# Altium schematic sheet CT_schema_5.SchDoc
size 454 x 443 mm
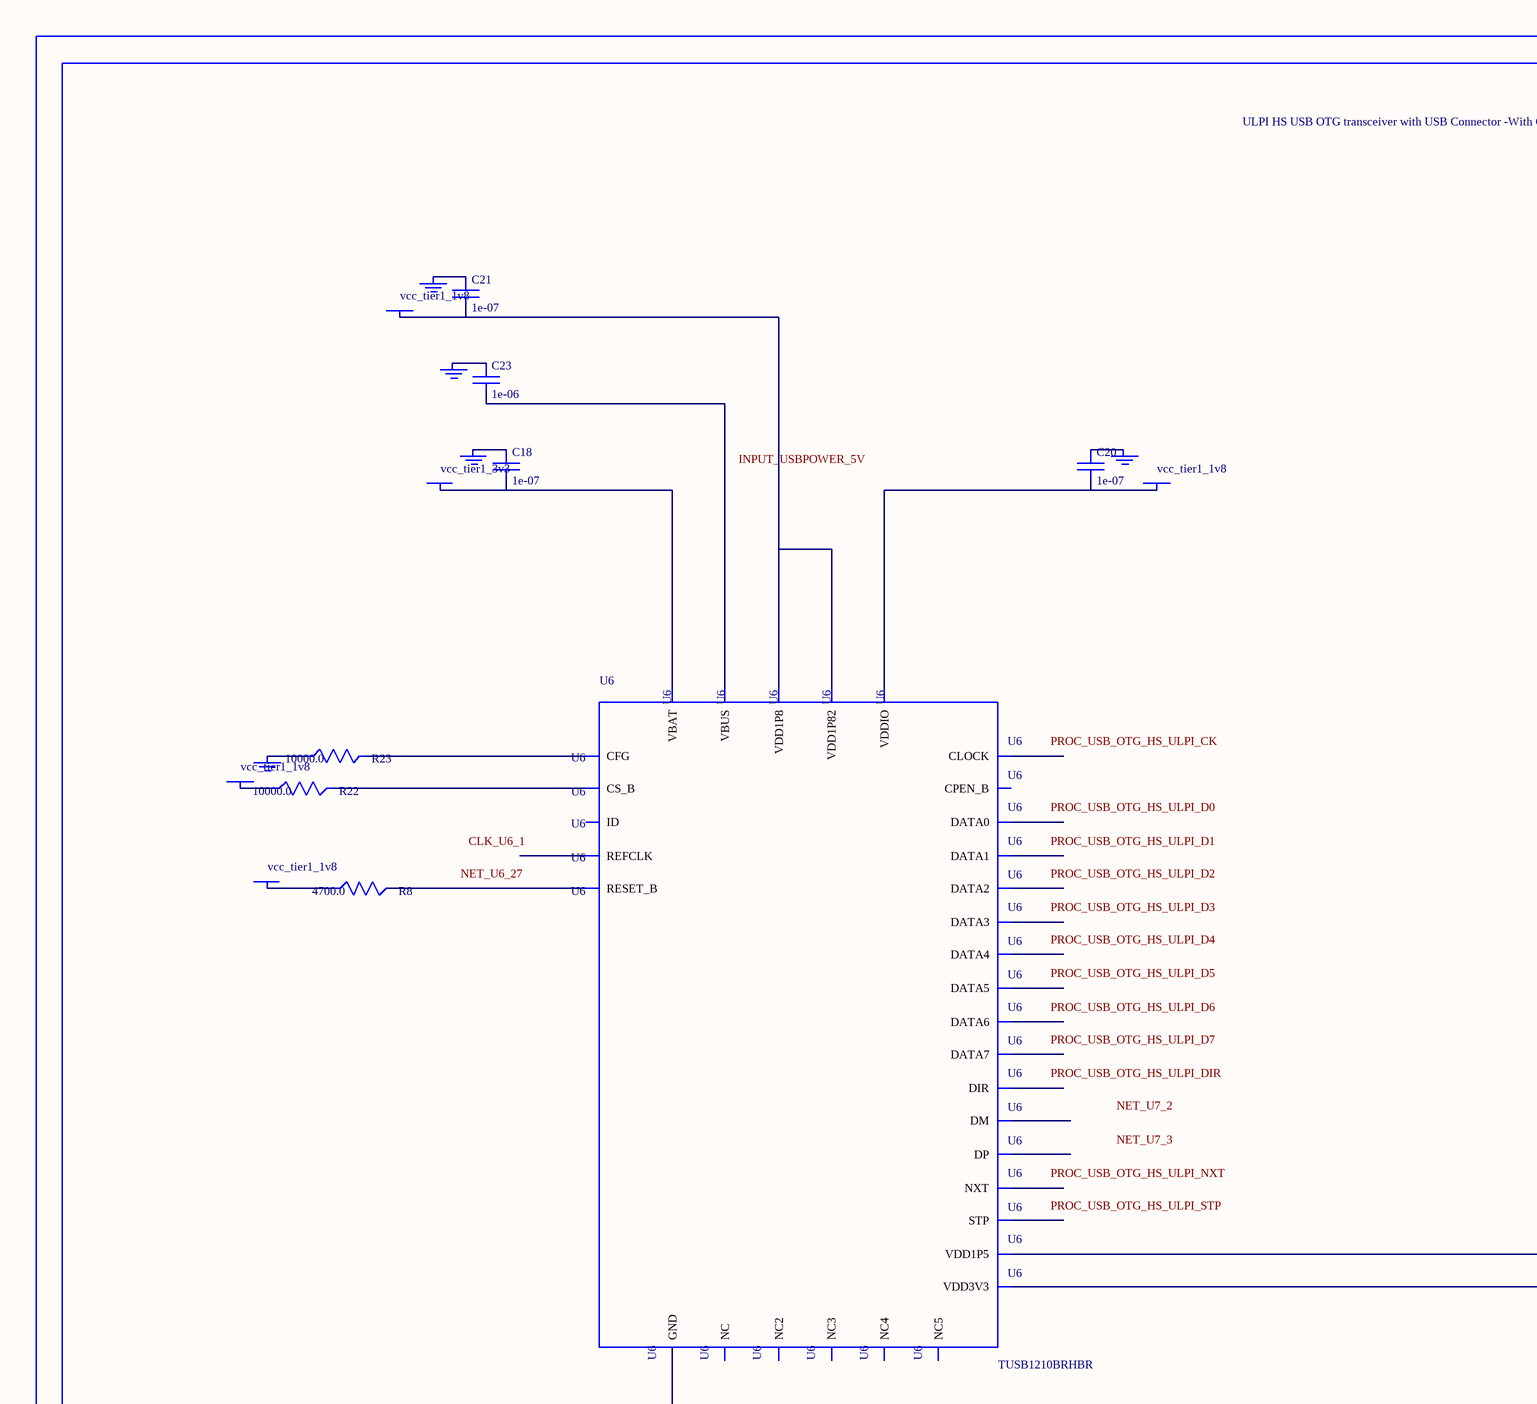
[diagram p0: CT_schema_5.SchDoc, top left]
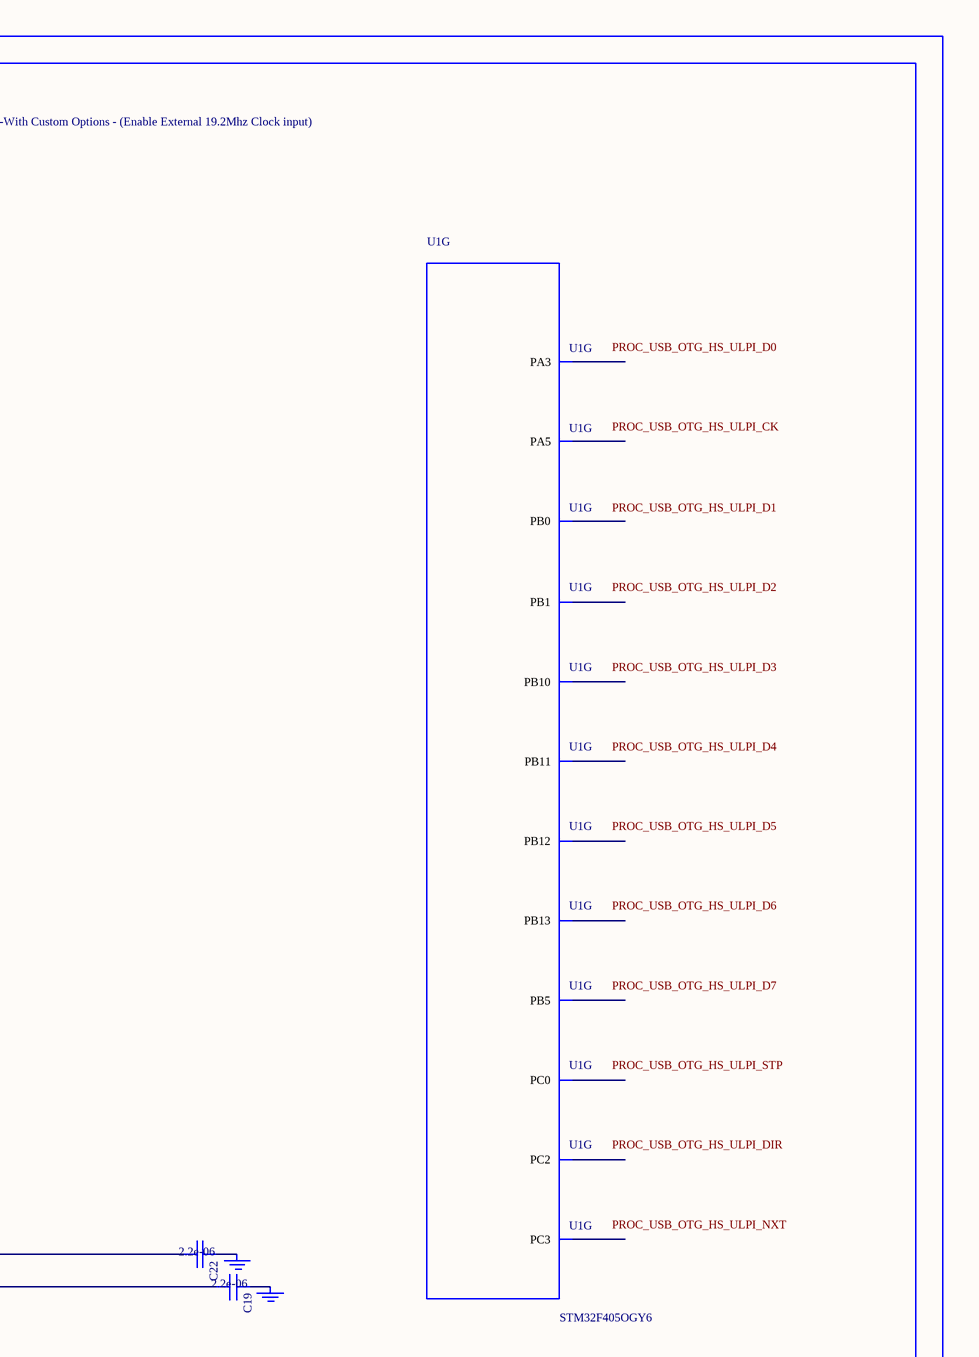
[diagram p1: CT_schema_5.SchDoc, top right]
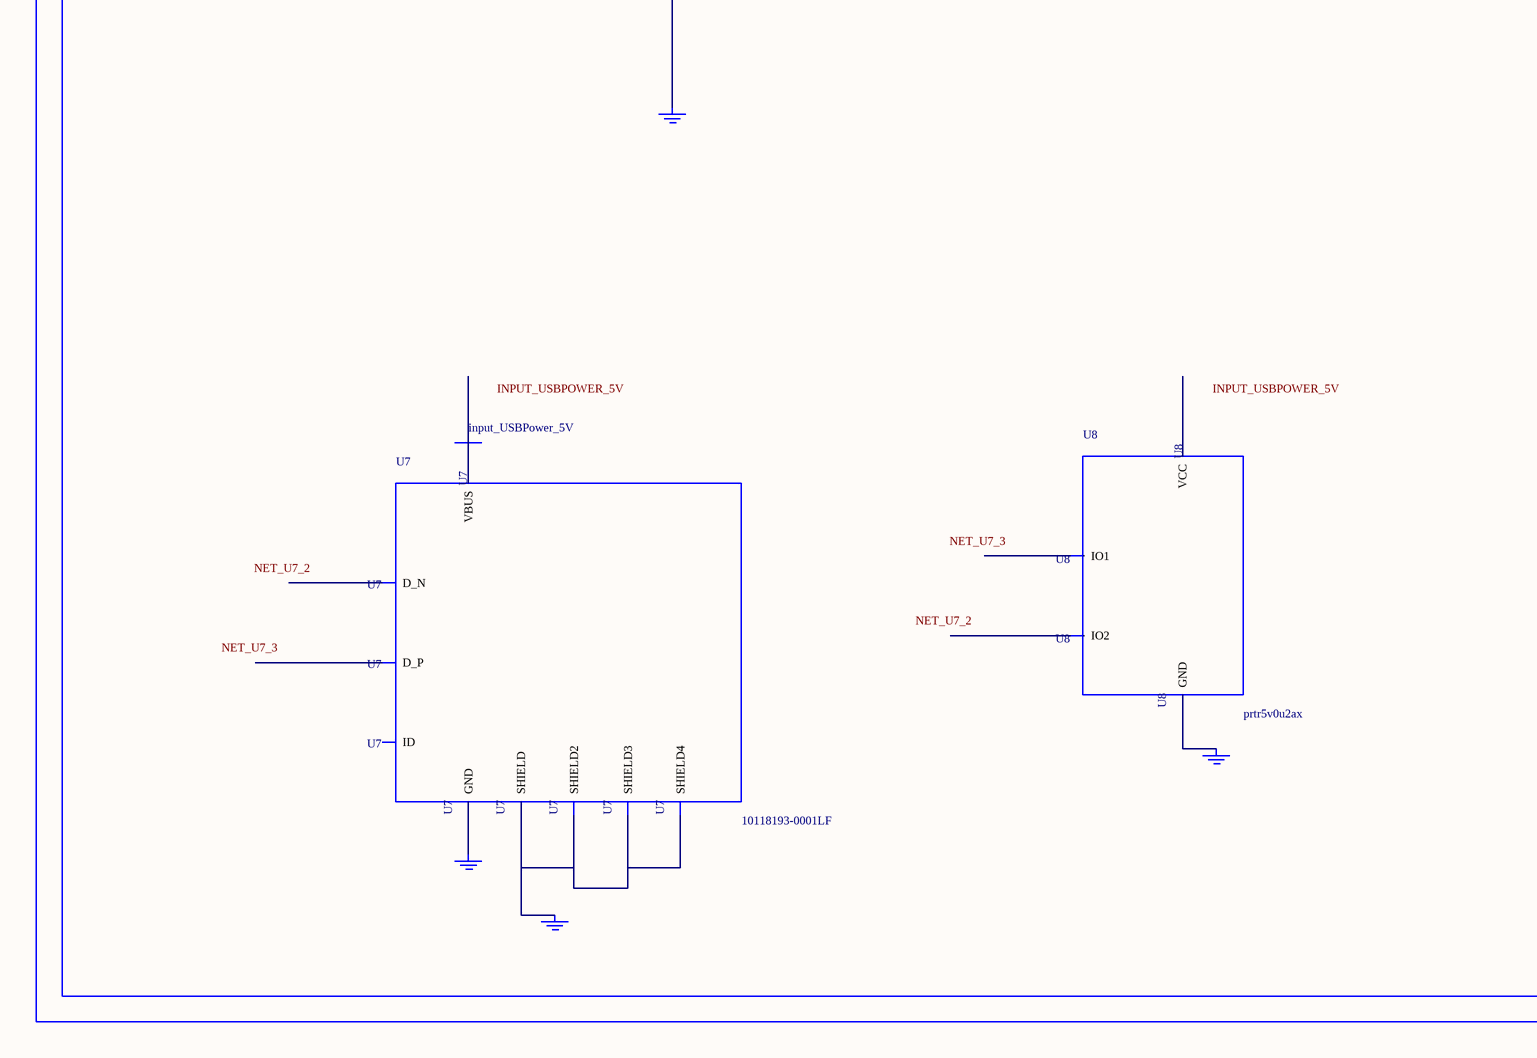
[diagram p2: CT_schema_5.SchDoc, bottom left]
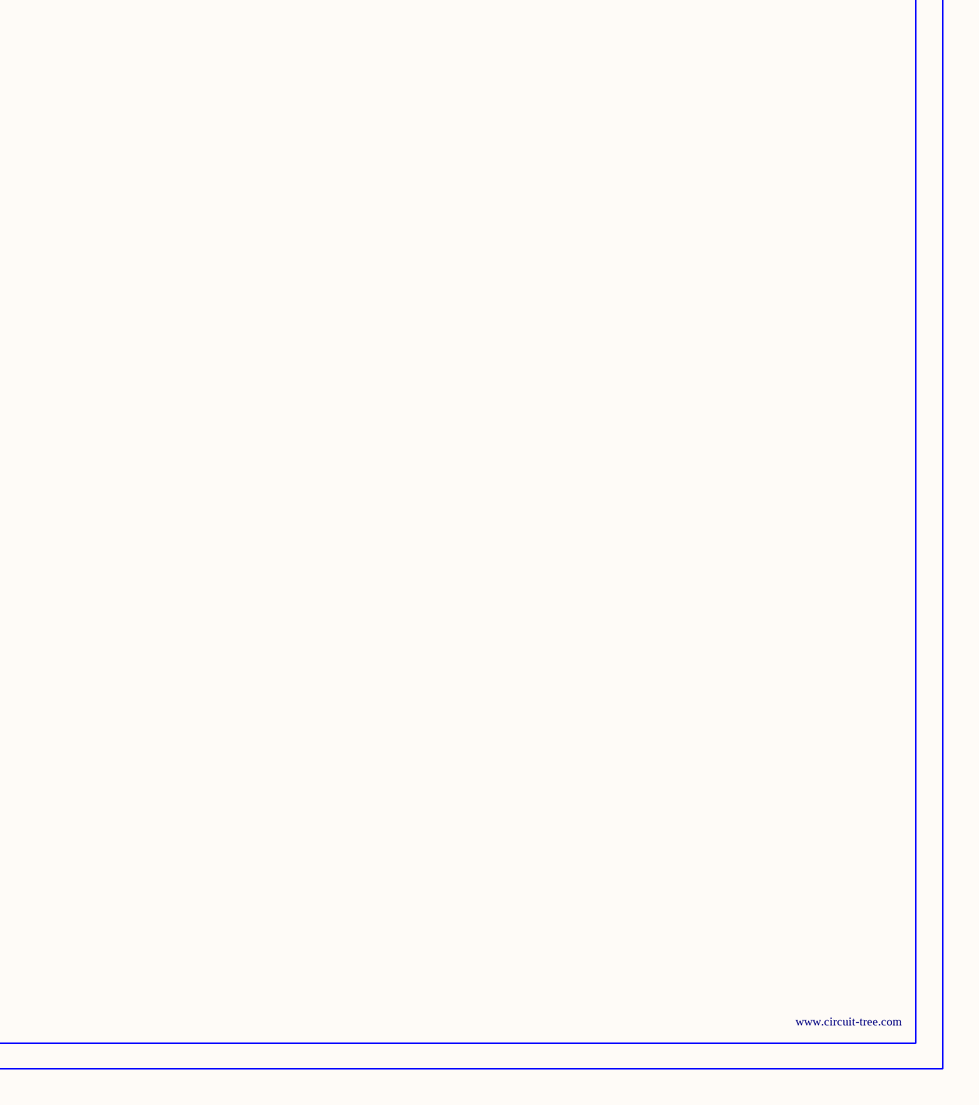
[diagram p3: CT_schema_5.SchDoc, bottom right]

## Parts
BORDER4  (no value)
C18  1e-07  [C0402]
C19  2.2e-06  [C0603]
C20  1e-07  [C0402]
C21  1e-07  [C0402]
C22  2.2e-06  [C0603]
C23  1e-06  [C0603]
GND_INSTANCE_4_0  (no value)
GND_INSTANCE_4_1  (no value)
GND_INSTANCE_4_2  (no value)
GND_INSTANCE_4_3  (no value)
GND_INSTANCE_4_4  (no value)
GND_INSTANCE_4_5  (no value)
GND_INSTANCE_4_6  (no value)
GND_INSTANCE_4_7  (no value)
GND_INSTANCE_4_8  (no value)
GND_INSTANCE_4_9  (no value)
GND_INSTANCE_4_10  (no value)
POWER_INSTANCE_4_0  vcc_tier1_1v8
POWER_INSTANCE_4_1  vcc_tier1_3v3
POWER_INSTANCE_4_2  vcc_tier1_1v8
POWER_INSTANCE_4_3  vcc_tier1_1v8
POWER_INSTANCE_4_4  vcc_tier1_1v8
POWER_INSTANCE_4_5  input_USBPower_5V
R8  4700.0  [R0603]
R22  10000.0  [R0603]
R23  10000.0  [R0603]
U1  STM32F405OGY6  [WLCSP90]  (part G of 9)
U6  TUSB1210BRHBR  [RHB32_3P45X3P45]
U7  10118193-0001LF  [FCI_10118193-0001LF]
U8  prtr5v0u2ax  [SOT143B]

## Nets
NetC18_1: C18.1 GND_INSTANCE_4_3.0(GND)
NetC18_2: C18.2 POWER_INSTANCE_4_1.0(PWR) U6.21(VBAT)
NetC19_1: C19.1 GND_INSTANCE_4_2.0(GND)
NetC19_2: C19.2 U6.20(VDD3V3)
NetC20_1: C20.1 GND_INSTANCE_4_6.0(GND)
NetC20_2: C20.2 POWER_INSTANCE_4_3.0(PWR) U6.32(VDDIO)
NetC21_1: C21.1 GND_INSTANCE_4_5.0(GND)
NetC21_2: C21.2 POWER_INSTANCE_4_2.0(PWR) U6.28(VDD1P8) U6.30(VDD1P82)
NetC22_1: C22.1 GND_INSTANCE_4_0.0(GND)
NetC22_2: C22.2 U6.12(VDD1P5)
NetC23_1: C23.1 GND_INSTANCE_4_4.0(GND)
NetC23_2: C23.2 U6.22(VBUS)
NetGND_INSTANCE_4_1_0: GND_INSTANCE_4_1.0(GND) R23.1
NetGND_INSTANCE_4_7_0: GND_INSTANCE_4_7.0(GND) U6.33(GND)
NetGND_INSTANCE_4_8_0: GND_INSTANCE_4_8.0(GND) U7.6(SHIELD) U7.7(SHIELD2) U7.8(SHIELD3) U7.9(SHIELD4)
NetGND_INSTANCE_4_9_0: GND_INSTANCE_4_9.0(GND) U7.5(GND)
NetGND_INSTANCE_4_10_0: GND_INSTANCE_4_10.0(GND) U8.1(GND)
NetPOWER_INSTANCE_4_0_0: POWER_INSTANCE_4_0.0(PWR) R22.1
NetPOWER_INSTANCE_4_4_0: POWER_INSTANCE_4_4.0(PWR) R8.1
NetPOWER_INSTANCE_4_5_0: POWER_INSTANCE_4_5.0(PWR) U7.1(VBUS)
NetR8_2: R8.2 U6.27(RESET_B)
NetR22_2: R22.2 U6.11(CS_B)
NetR23_2: R23.2 U6.14(CFG)

Not connected (* = marked no-connect by the designer): U1 D7(PB5) D10(PC2) E9(PC3) E10(PC0) G7(PB0) G8(PA5) H4(PB10) H7(PB1) H9(PA3) J1(PB13) J3(PB12) J4(PB11); U6 1(REFCLK) 2(NXT) 3(DATA0) 4(DATA1) 5(DATA2) 6(DATA3) 7(DATA4) 8(NC) 9(DATA5) 10(DATA6) 13(DATA7) 15(NC2) 16(NC3) 17(CPEN_B) 18(DP) 19(DM) 23(ID) 24(NC4) 25(NC5) 26(CLOCK) 29(STP) 31(DIR); U7 2(D_N) 3(D_P) 4(ID); U8 2(IO1) 3(IO2) 4(VCC)

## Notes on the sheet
- Labels drawn without touching a wire or pin: CLK_U6_1, INPUT_USBPOWER_5V, NET_U6_27, NET_U7_2, NET_U7_3, PROC_USB_OTG_HS_ULPI_CK, PROC_USB_OTG_HS_ULPI_D0, PROC_USB_OTG_HS_ULPI_D1, PROC_USB_OTG_HS_ULPI_D2, PROC_USB_OTG_HS_ULPI_D3, PROC_USB_OTG_HS_ULPI_D4, PROC_USB_OTG_HS_ULPI_D5, PROC_USB_OTG_HS_ULPI_D6, PROC_USB_OTG_HS_ULPI_D7, PROC_USB_OTG_HS_ULPI_DIR, PROC_USB_OTG_HS_ULPI_NXT, PROC_USB_OTG_HS_ULPI_STP

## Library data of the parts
BORDER4 = BORDER_PAGE4
C18 C20 C21 = C0402C104K3RACTU
C19 C22 = C0603C225K8RACTU
C23 = C0603C105K3RACTU
GND_INSTANCE_4_0-GND_INSTANCE_4_10 = GND
POWER_INSTANCE_4_0-POWER_INSTANCE_4_5 = PWR
R8 = RC0603JR-074K7L
R22 R23 = RC0603JR-0710KL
